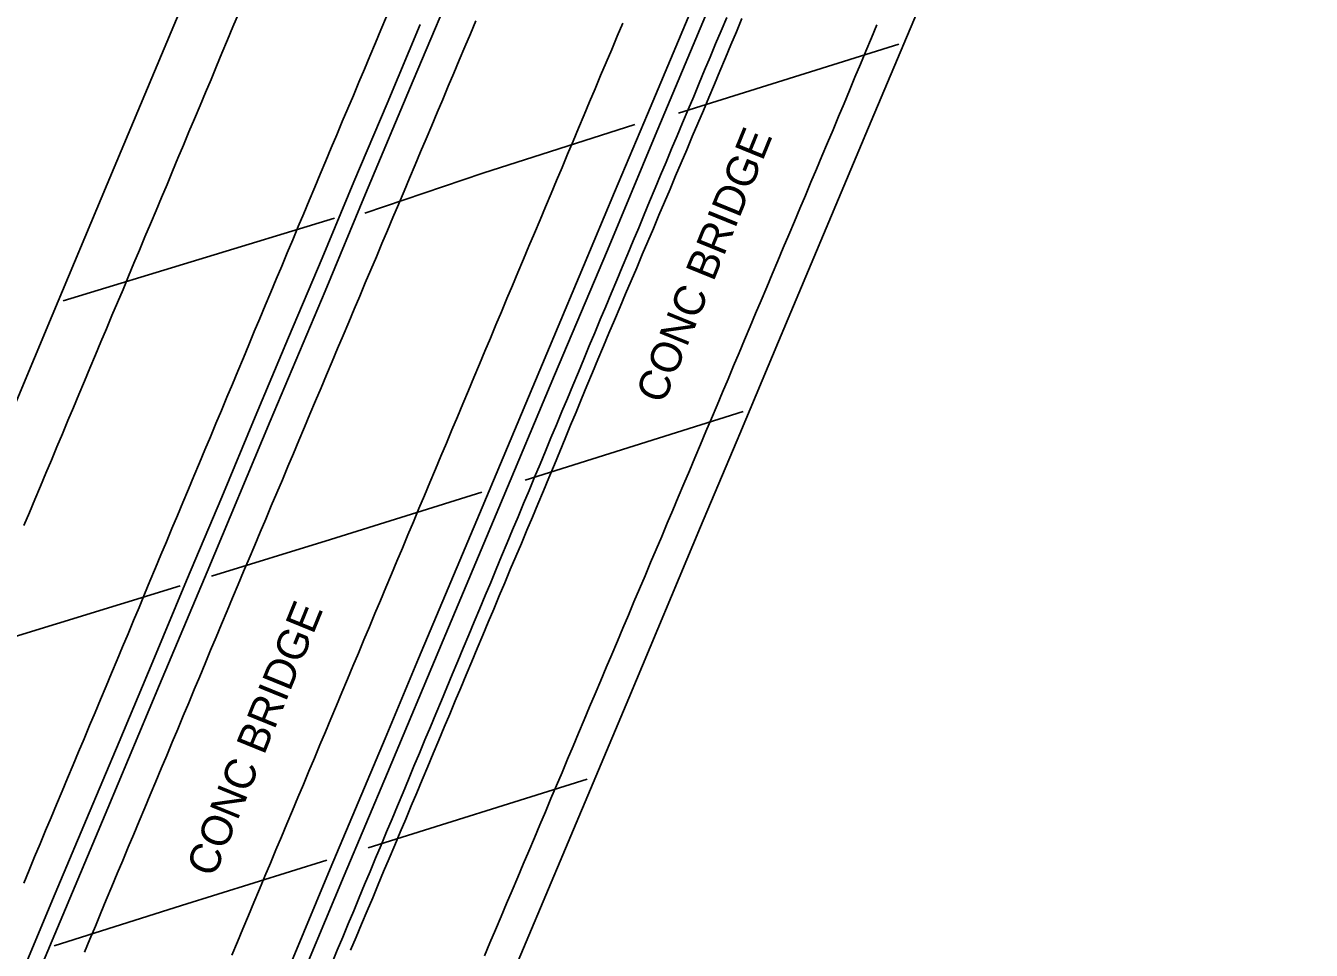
# Model space of a CAD drawing. Extents: x 1948091 to 1975253, y 787267 to 823306.
# Drawn here: x 1968636.1 to 1968861.9, y 796985.5 to 797147.9 of the extents above; entities that cross this region are included whole.
import ezdxf

# ---------------------------------------------------------------- set-up
doc = ezdxf.new("R2010")
doc.units = 0
for name, color, linetype in [('RD_EX_Bridge', 7, 'Continuous'), ('RD_EX_Bridge_Seam', 7, 'Continuous'), ('RD_EX_Pavement_Markings', 7, 'Continuous'), ('RD_TX_RoadID', 7, 'Continuous')]:
    doc.layers.add(name, color=color, linetype=linetype)

msp = doc.modelspace()

# ---------------------------------------------------------------- linework, layer by layer
at = {"layer": 'RD_EX_Bridge'}
for points in [[(1968718.87, 796974.81), (1968724.02, 796987.01), (1968730.9, 797003.4), (1968742.02, 797029.84), (1968754.63, 797059.88), (1968761.53, 797076.23), (1968768.34, 797092.46), (1968774.05, 797106.11), (1968784.61, 797131.18), (1968792.07, 797148.89), (1968801.73, 797171.89), (1968811.78, 797195.82), (1968817.45, 797209.32), (1968823.38, 797223.44), (1968828.4, 797235.39), (1968834.54, 797250.07), (1968840.72, 797264.73), (1968847.09, 797279.99), (1968855.72, 797300.5), (1968861.92, 797315.18)], [(1968775.7, 797308.74), (1968772.06, 797300), (1968764.72, 797282.58), (1968757.14, 797264.43), (1968749.29, 797245.86), (1968739.99, 797223.47), (1968730.91, 797201.98), (1968720.61, 797177.34), (1968712.63, 797158.38), (1968704.16, 797138.28), (1968695.75, 797118.37), (1968688.66, 797101.29), (1968679.02, 797078.46), (1968667.95, 797051.99), (1968659.58, 797032.13), (1968650.49, 797010.51), (1968639.02, 796983.23)], [(1968822.3, 797308.47), (1968812.17, 797284.4), (1968804.02, 797265.06), (1968795.49, 797244.8), (1968787.36, 797225.51), (1968779.29, 797206.18), (1968771.36, 797187.35), (1968762.78, 797166.96), (1968755.49, 797149.67), (1968746.66, 797128.62), (1968738.26, 797108.53), (1968728.95, 797086.56), (1968719.2, 797063.27), (1968709.41, 797040.03), (1968699.62, 797016.72), (1968692.05, 796998.66), (1968682.47, 796975.84)], [(1968667.69, 797161.27), (1968658.71, 797139.88), (1968650.4, 797120.08), (1968640.73, 797097.02), (1968631.34, 797074.74)], [(1968682.46, 796982.81), (1968689.57, 796999.83), (1968694.01, 797010.38), (1968699.22, 797022.74), (1968705.1, 797036.79), (1968710.3, 797049.12), (1968716.26, 797063.33), (1968723.2, 797079.77), (1968728.86, 797093.26), (1968734.06, 797105.69), (1968739.51, 797118.7), (1968745.29, 797132.36), (1968750.74, 797145.33), (1968754.73, 797154.87)], [(1968759.22, 797149.34), (1968758.25, 797147.03), (1968757.28, 797144.72), (1968756.32, 797142.42), (1968755.35, 797140.11), (1968754.38, 797137.81), (1968753.42, 797135.5), (1968752.45, 797133.2), (1968751.48, 797130.89), (1968750.52, 797128.59), (1968749.55, 797126.28), (1968748.58, 797123.98), (1968747.62, 797121.67), (1968746.65, 797119.37), (1968745.68, 797117.06), (1968744.72, 797114.75), (1968743.76, 797112.45), (1968742.79, 797110.14), (1968741.83, 797107.83), (1968740.87, 797105.53), (1968739.91, 797103.22), (1968738.94, 797100.91), (1968737.98, 797098.6), (1968737.02, 797096.3), (1968736.05, 797093.99), (1968735.09, 797091.68), (1968734.13, 797089.38), (1968733.17, 797087.07), (1968732.2, 797084.76), (1968731.24, 797082.45), (1968730.28, 797080.15), (1968729.32, 797077.84), (1968728.35, 797075.53), (1968727.39, 797073.22), (1968726.43, 797070.92), (1968725.47, 797068.61), (1968724.5, 797066.3), (1968723.54, 797064), (1968722.58, 797061.69), (1968721.61, 797059.38), (1968720.65, 797057.07), (1968719.69, 797054.77), (1968718.73, 797052.46), (1968717.76, 797050.15), (1968716.8, 797047.85), (1968715.84, 797045.54), (1968714.88, 797043.23), (1968713.91, 797040.92), (1968712.95, 797038.62), (1968711.99, 797036.31), (1968711.02, 797034), (1968710.06, 797031.7), (1968709.1, 797029.39), (1968708.14, 797027.08), (1968707.17, 797024.77), (1968706.21, 797022.47), (1968705.25, 797020.16), (1968704.29, 797017.85), (1968703.32, 797015.55), (1968702.36, 797013.24), (1968701.4, 797010.93), (1968700.43, 797008.62), (1968699.47, 797006.32), (1968698.51, 797004.01), (1968697.55, 797001.7), (1968696.58, 796999.39), (1968695.62, 796997.09), (1968694.66, 796994.78), (1968693.7, 796992.47), (1968692.73, 796990.17), (1968691.77, 796987.86), (1968690.81, 796985.55), (1968689.85, 796983.24)], [(1968635.79, 796982.45), (1968641.28, 796995.49), (1968646.76, 797008.56), (1968652.47, 797022.14), (1968658.4, 797036.27), (1968664.32, 797050.51), (1968670.52, 797065.13), (1968676.39, 797079.21), (1968682.27, 797093.19), (1968688.15, 797107.09), (1968693.71, 797120.51), (1968699.56, 797134.29), (1968705.4, 797148.11)]]:
    msp.add_lwpolyline(points, dxfattribs=at)
at = {"layer": 'RD_EX_Bridge_Seam'}
for p, q in [((1968789.49, 797144.7), (1968750.73, 797132.57)), ((1968690.32, 797114.12), (1968642.65, 797099.6)), ((1968762.11, 797080.16), (1968723.79, 797068.11)), ((1968663.2, 797049.56), (1968615.39, 797034.89)), ((1968734.71, 797015.59), (1968696.21, 797003.55))]:
    msp.add_line(p, q, dxfattribs=at)
for points in [[(1968743.08, 797130.6), (1968716.39, 797122.05), (1968695.64, 797115.01)], [(1968716.18, 797065.97), (1968689.6, 797057.67), (1968668.7, 797051.27)], [(1968688.96, 797001.38), (1968663.42, 796993.41), (1968641.1, 796986.3)]]:
    msp.add_lwpolyline(points, dxfattribs=at)
at = {"layer": 'RD_EX_Pavement_Markings'}
for points in [[(1968699.45, 797149.52), (1968698.49, 797147.21), (1968697.52, 797144.91), (1968696.55, 797142.6), (1968695.58, 797140.3), (1968694.61, 797137.99), (1968693.64, 797135.69), (1968692.67, 797133.38), (1968691.7, 797131.08), (1968690.73, 797128.77), (1968689.76, 797126.47), (1968688.8, 797124.17), (1968687.83, 797121.86), (1968686.86, 797119.56), (1968685.89, 797117.25), (1968684.92, 797114.95), (1968683.95, 797112.64), (1968682.99, 797110.34), (1968682.02, 797108.03), (1968681.06, 797105.72), (1968680.09, 797103.42), (1968679.13, 797101.11), (1968678.16, 797098.8), (1968677.2, 797096.5), (1968676.24, 797094.19), (1968675.27, 797091.89), (1968674.31, 797089.58), (1968673.34, 797087.27), (1968672.38, 797084.97), (1968671.41, 797082.66), (1968670.45, 797080.35), (1968669.49, 797078.05), (1968668.52, 797075.74), (1968667.56, 797073.43), (1968666.59, 797071.13), (1968665.63, 797068.82), (1968664.66, 797066.51), (1968663.7, 797064.21), (1968662.74, 797061.9), (1968661.77, 797059.59), (1968660.81, 797057.29), (1968659.84, 797054.98), (1968658.88, 797052.68), (1968657.91, 797050.37), (1968656.95, 797048.06), (1968655.99, 797045.76), (1968655.02, 797043.45), (1968654.06, 797041.14), (1968653.09, 797038.84), (1968652.13, 797036.53), (1968651.16, 797034.22), (1968650.2, 797031.92), (1968649.23, 797029.61), (1968648.27, 797027.31), (1968647.3, 797025), (1968646.34, 797022.69), (1968645.37, 797020.39), (1968644.41, 797018.08), (1968643.44, 797015.77), (1968642.48, 797013.47), (1968641.51, 797011.16), (1968640.55, 797008.86), (1968639.58, 797006.55), (1968638.62, 797004.24), (1968637.65, 797001.94), (1968636.69, 796999.63), (1968635.72, 796997.32)], [(1968673.46, 797150.03), (1968672.49, 797147.72), (1968671.53, 797145.42), (1968670.56, 797143.11), (1968669.6, 797140.81), (1968668.63, 797138.5), (1968667.66, 797136.2), (1968666.7, 797133.89), (1968665.73, 797131.58), (1968664.76, 797129.28), (1968663.8, 797126.97), (1968662.83, 797124.67), (1968661.86, 797122.36), (1968660.9, 797120.06), (1968659.93, 797117.75), (1968658.97, 797115.45), (1968658, 797113.14), (1968657.03, 797110.83), (1968656.07, 797108.53), (1968655.1, 797106.22), (1968654.13, 797103.92), (1968653.17, 797101.61), (1968652.2, 797099.31), (1968651.23, 797097), (1968650.27, 797094.7), (1968649.3, 797092.39), (1968648.33, 797090.09), (1968647.36, 797087.78), (1968646.4, 797085.47), (1968645.43, 797083.17), (1968644.46, 797080.86), (1968643.5, 797078.56), (1968642.53, 797076.25), (1968641.56, 797073.95), (1968640.59, 797071.64), (1968639.63, 797069.34), (1968638.66, 797067.03), (1968637.69, 797064.73), (1968636.73, 797062.42), (1968635.76, 797060.12)], [(1968715.16, 797148.81), (1968714.19, 797146.51), (1968713.22, 797144.2), (1968712.25, 797141.9), (1968711.28, 797139.59), (1968710.31, 797137.29), (1968709.34, 797134.99), (1968708.37, 797132.68), (1968707.4, 797130.38), (1968706.43, 797128.07), (1968705.46, 797125.77), (1968704.49, 797123.47), (1968703.52, 797121.16), (1968702.55, 797118.86), (1968701.58, 797116.55), (1968700.6, 797114.25), (1968699.63, 797111.95), (1968698.66, 797109.65), (1968697.69, 797107.34), (1968696.71, 797105.04), (1968695.74, 797102.74), (1968694.77, 797100.43), (1968693.8, 797098.13), (1968692.83, 797095.83), (1968691.85, 797093.52), (1968690.88, 797091.22), (1968689.91, 797088.92), (1968688.94, 797086.61), (1968687.96, 797084.31), (1968686.99, 797082.01), (1968686.02, 797079.7), (1968685.05, 797077.4), (1968684.08, 797075.1), (1968683.1, 797072.79), (1968682.13, 797070.49), (1968681.16, 797068.19), (1968680.19, 797065.89), (1968679.21, 797063.58), (1968678.24, 797061.28), (1968677.27, 797058.98), (1968676.3, 797056.67), (1968675.33, 797054.37), (1968674.36, 797052.06), (1968673.4, 797049.76), (1968672.43, 797047.45), (1968671.47, 797045.14), (1968670.5, 797042.84), (1968669.54, 797040.53), (1968668.57, 797038.23), (1968667.61, 797035.92), (1968666.64, 797033.61), (1968665.68, 797031.31), (1968664.71, 797029), (1968663.75, 797026.69), (1968662.78, 797024.39), (1968661.82, 797022.08), (1968660.86, 797019.77), (1968659.89, 797017.47), (1968658.93, 797015.16), (1968657.96, 797012.86), (1968657, 797010.55), (1968656.03, 797008.24), (1968655.07, 797005.94), (1968654.1, 797003.63), (1968653.14, 797001.32), (1968652.17, 796999.02), (1968651.21, 796996.71), (1968650.24, 796994.4), (1968649.28, 796992.1), (1968648.31, 796989.79), (1968647.35, 796987.49), (1968646.38, 796985.18)], [(1968761.89, 797149.18), (1968760.93, 797146.87), (1968759.96, 797144.57), (1968759, 797142.26), (1968758.04, 797139.95), (1968757.07, 797137.65), (1968756.1, 797135.34), (1968755.13, 797133.04), (1968754.15, 797130.74), (1968753.18, 797128.44), (1968752.2, 797126.14), (1968751.23, 797123.83), (1968750.25, 797121.53), (1968749.28, 797119.23), (1968748.3, 797116.93), (1968747.33, 797114.63), (1968746.35, 797112.32), (1968745.38, 797110.02), (1968744.4, 797107.72), (1968743.43, 797105.42), (1968742.45, 797103.12), (1968741.47, 797100.82), (1968740.49, 797098.52), (1968739.51, 797096.22), (1968738.53, 797093.92), (1968737.56, 797091.62), (1968736.58, 797089.32), (1968735.62, 797087.01), (1968734.66, 797084.7), (1968733.71, 797082.38), (1968732.76, 797080.07), (1968731.8, 797077.76), (1968730.85, 797075.45), (1968729.9, 797073.14), (1968728.95, 797070.83), (1968727.98, 797068.52), (1968727.02, 797066.22), (1968726.05, 797063.91), (1968725.08, 797061.61), (1968724.11, 797059.3), (1968723.15, 797057), (1968722.18, 797054.69), (1968721.21, 797052.39), (1968720.24, 797050.08), (1968719.28, 797047.77), (1968718.31, 797045.47), (1968717.34, 797043.16), (1968716.37, 797040.86), (1968715.41, 797038.55), (1968714.44, 797036.25), (1968713.47, 797033.94), (1968712.51, 797031.64), (1968711.54, 797029.33), (1968710.57, 797027.03), (1968709.6, 797024.72), (1968708.64, 797022.42), (1968707.67, 797020.11), (1968706.7, 797017.81), (1968705.73, 797015.5), (1968704.77, 797013.2), (1968703.8, 797010.89), (1968702.83, 797008.59), (1968701.86, 797006.28), (1968700.9, 797003.98), (1968699.93, 797001.67), (1968698.96, 796999.37), (1968698, 796997.06), (1968697.03, 796994.75), (1968696.06, 796992.45), (1968695.09, 796990.14), (1968694.13, 796987.84), (1968693.16, 796985.53)], [(1968740.97, 797148.38), (1968740, 797146.08), (1968739.02, 797143.77), (1968738.05, 797141.47), (1968737.08, 797139.17), (1968736.11, 797136.86), (1968735.14, 797134.56), (1968734.17, 797132.25), (1968733.2, 797129.95), (1968732.23, 797127.65), (1968731.26, 797125.34), (1968730.3, 797123.04), (1968729.33, 797120.73), (1968728.36, 797118.43), (1968727.4, 797116.12), (1968726.43, 797113.82), (1968725.46, 797111.51), (1968724.49, 797109.21), (1968723.53, 797106.9), (1968722.56, 797104.6), (1968721.59, 797102.29), (1968720.62, 797099.99), (1968719.66, 797097.68), (1968718.69, 797095.37), (1968717.72, 797093.07), (1968716.75, 797090.76), (1968715.79, 797088.46), (1968714.82, 797086.15), (1968713.85, 797083.85), (1968712.89, 797081.54), (1968711.92, 797079.24), (1968710.95, 797076.93), (1968709.98, 797074.63), (1968709.02, 797072.32), (1968708.05, 797070.02), (1968707.08, 797067.71), (1968706.11, 797065.41), (1968705.15, 797063.1), (1968704.18, 797060.8), (1968703.21, 797058.49), (1968702.25, 797056.18), (1968701.28, 797053.88), (1968700.32, 797051.57), (1968699.35, 797049.27), (1968698.38, 797046.96), (1968697.42, 797044.66), (1968696.45, 797042.35), (1968695.48, 797040.05), (1968694.52, 797037.74), (1968693.55, 797035.43), (1968692.59, 797033.13), (1968691.62, 797030.82), (1968690.65, 797028.52), (1968689.69, 797026.21), (1968688.72, 797023.91), (1968687.76, 797021.6), (1968686.79, 797019.29), (1968685.82, 797016.99), (1968684.86, 797014.68), (1968683.89, 797012.38), (1968682.92, 797010.07), (1968681.96, 797007.77), (1968680.99, 797005.46), (1968680.03, 797003.15), (1968679.06, 797000.85), (1968678.09, 796998.54), (1968677.13, 796996.24), (1968676.16, 796993.93), (1968675.2, 796991.62), (1968674.23, 796989.32), (1968673.27, 796987.01), (1968672.3, 796984.7)], [(1968785.61, 797148.09), (1968784.65, 797145.79), (1968783.69, 797143.48), (1968782.72, 797141.17), (1968781.76, 797138.87), (1968780.79, 797136.56), (1968779.83, 797134.26), (1968778.86, 797131.95), (1968777.9, 797129.64), (1968776.93, 797127.34), (1968775.96, 797125.03), (1968774.99, 797122.73), (1968774.02, 797120.43), (1968773.05, 797118.12), (1968772.08, 797115.82), (1968771.11, 797113.52), (1968770.14, 797111.21), (1968769.17, 797108.91), (1968768.19, 797106.6), (1968767.22, 797104.3), (1968766.25, 797102), (1968765.28, 797099.69), (1968764.31, 797097.39), (1968763.34, 797095.09), (1968762.37, 797092.78), (1968761.4, 797090.48), (1968760.43, 797088.17), (1968759.46, 797085.87), (1968758.49, 797083.57), (1968757.52, 797081.26), (1968756.55, 797078.96), (1968755.58, 797076.66), (1968754.6, 797074.35), (1968753.63, 797072.05), (1968752.66, 797069.75), (1968751.69, 797067.44), (1968750.71, 797065.14), (1968749.74, 797062.84), (1968748.77, 797060.53), (1968747.8, 797058.23), (1968746.82, 797055.93), (1968745.85, 797053.63), (1968744.88, 797051.32), (1968743.91, 797049.02), (1968742.93, 797046.72), (1968741.96, 797044.41), (1968740.99, 797042.11), (1968740.02, 797039.81), (1968739.04, 797037.5), (1968738.07, 797035.2), (1968737.1, 797032.9), (1968736.13, 797030.59), (1968735.15, 797028.29), (1968734.18, 797025.99), (1968733.21, 797023.69), (1968732.24, 797021.38), (1968731.26, 797019.08), (1968730.29, 797016.78), (1968729.32, 797014.47), (1968728.34, 797012.17), (1968727.37, 797009.87), (1968726.4, 797007.56), (1968725.43, 797005.26), (1968724.45, 797002.96), (1968723.48, 797000.66), (1968722.51, 796998.35), (1968721.53, 796996.05), (1968720.56, 796993.75), (1968719.59, 796991.44), (1968718.62, 796989.14), (1968717.64, 796986.84), (1968716.67, 796984.54)]]:
    msp.add_lwpolyline(points, dxfattribs=at)

# ---------------------------------------------------------------- texts
at = {"layer": 'RD_TX_RoadID'}
for p in [(1968748.11, 797081.28), (1968669.17, 796998.13)]:
    msp.add_text('CONC BRIDGE', height=5.4, rotation=67.8596, dxfattribs=at).set_placement(p)

doc.saveas('drawing.dxf')
